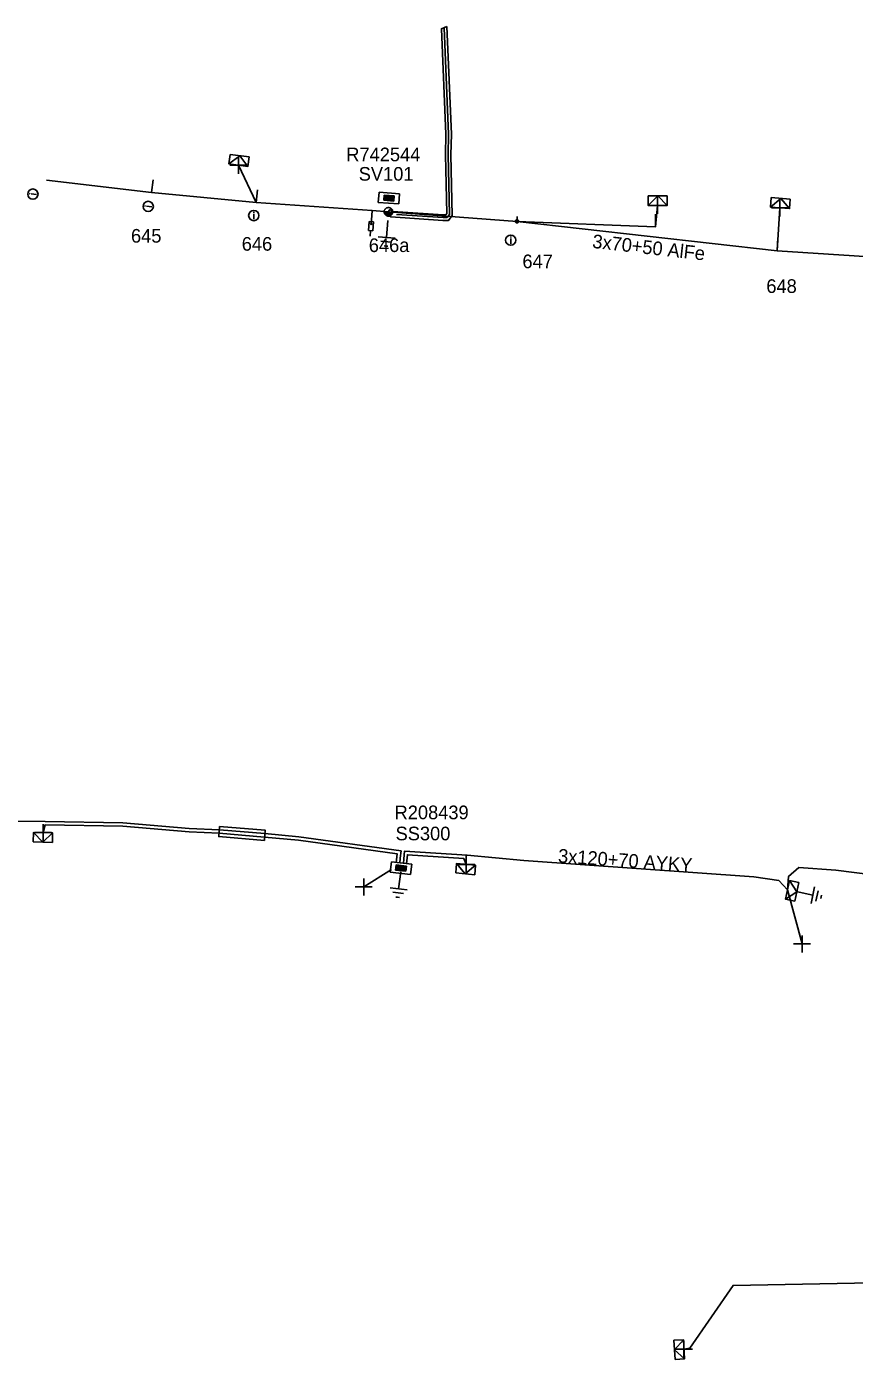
# Model space of a CAD drawing. Extents: x -540466 to -537383, y -1184038 to -1179972.
# Drawn here: x -538715.9 to -538655.3, y -1180219.4 to -1180121.7 of the extents above; entities that cross this region are included whole.
import ezdxf

# ---------------------------------------------------------------- set-up
doc = ezdxf.new("R2010")
doc.units = 0
for name, color, linetype in [('Vrstva 1', 7, 'Continuous'), ('Vrstva 10', 7, 'Continuous'), ('Vrstva 13', 7, 'Continuous'), ('Vrstva 14', 7, 'Continuous'), ('Vrstva 15', 7, 'Continuous'), ('Vrstva 16', 7, 'Continuous'), ('Vrstva 2', 7, 'Continuous'), ('Vrstva 20', 7, 'Continuous'), ('Vrstva 28', 7, 'Continuous'), ('Vrstva 29', 7, 'Continuous'), ('Vrstva 30', 7, 'Continuous'), ('Vrstva 31', 7, 'Continuous'), ('Vrstva 34', 7, 'Continuous'), ('Vrstva 36', 7, 'Continuous'), ('Vrstva 5', 7, 'Continuous'), ('Vrstva 52', 7, 'Continuous'), ('Vrstva 54', 7, 'Continuous'), ('Vrstva 59', 7, 'Continuous'), ('Vrstva 6', 7, 'Continuous'), ('Vrstva 8', 7, 'Continuous'), ('Vrstva 9', 7, 'Continuous')]:
    doc.layers.add(name, color=color, linetype=linetype)

# ---------------------------------------------------------------- blocks, each defined once
blk = doc.blocks.new('NN440')
at = {"layer": 'Vrstva 2'}
for points in [[(0.63, 0), (0.63, 0.06), (0.62, 0.13), (0.6, 0.19), (0.58, 0.25), (0.55, 0.31), (0.51, 0.37), (0.47, 0.42), (0.42, 0.46), (0.37, 0.51), (0.32, 0.54), (0.26, 0.57), (0.2, 0.59), (0.13, 0.61), (0.07, 0.62), (0, 0.63), (-0.06, 0.62), (-0.13, 0.61), (-0.19, 0.59), (-0.26, 0.57), (-0.31, 0.54), (-0.37, 0.51), (-0.42, 0.46), (-0.47, 0.42), (-0.51, 0.37), (-0.54, 0.31), (-0.57, 0.25), (-0.6, 0.19), (-0.62, 0.13), (-0.63, 0.06), (-0.63, 0), (-0.63, -0.07), (-0.62, -0.14), (-0.6, -0.2), (-0.57, -0.26), (-0.54, -0.32), (-0.51, -0.37), (-0.47, -0.43), (-0.42, -0.47), (-0.37, -0.51), (-0.31, -0.55), (-0.26, -0.58), (-0.19, -0.6), (-0.13, -0.62), (-0.06, -0.63), (0, -0.63), (0.07, -0.63), (0.13, -0.62), (0.2, -0.6), (0.26, -0.58), (0.32, -0.55), (0.37, -0.51), (0.42, -0.47), (0.47, -0.43), (0.51, -0.37), (0.55, -0.32), (0.58, -0.26), (0.6, -0.2), (0.62, -0.14), (0.63, -0.07), (0.63, 0)], [(-0.63, 0), (0.63, 0)], [(-0.6, -0.18), (0.57, -0.18)], [(-0.51, -0.32), (0.5, -0.32)], [(-0.37, -0.47), (0.35, -0.47)]]:
    blk.add_lwpolyline(points, dxfattribs=at)
blk = doc.blocks.new('NN770')
at = {"layer": 'Vrstva 10'}
for p, q in [((0.002, 0.187), (0.002, 0.263)), ((0.002, -0.276), (0.002, 0.111))]:
    blk.add_line(p, q, dxfattribs=at)
blk.add_circle((0, -0.008), 0.375, dxfattribs=at)
blk = doc.blocks.new('NN800')
at = {"layer": 'Vrstva 1'}
for points in [[(-0.442, 0.442), (0.442, -0.442)], [(-0.442, -0.442), (0.442, 0.442)]]:
    blk.add_lwpolyline(points, dxfattribs=at)
blk = doc.blocks.new('NN820')
at = {"layer": 'Vrstva 13'}
for points in [[(-0.003, 0.004), (-0.003, -1.049)], [(-0.165, -0.813), (0.165, -0.813)], [(-0.165, -1.473), (-0.165, -0.813)], [(-0.003, -1.049), (-0.062, -0.926)], [(-0.003, -1.049), (0.057, -0.926)], [(0.165, -0.813), (0.165, -1.473)], [(0.165, -1.473), (-0.165, -1.473)], [(-0.003, -1.473), (-0.003, -1.871)]]:
    blk.add_lwpolyline(points, dxfattribs=at)
blk = doc.blocks.new('NN620')
at = {"layer": 'Vrstva 8'}
for points in [[(0.752, 0.004), (-0.748, 0.004)], [(-0.748, 0.004), (-0.748, -0.746)], [(0.752, -0.746), (0.752, 0.004)], [(-0.748, -0.746), (0.752, -0.746)], [(0.368, -0.18), (-0.376, -0.18)], [(-0.376, -0.18), (-0.376, -0.558)], [(-0.376, -0.558), (0.368, -0.558)], [(0.321, -0.227), (-0.329, -0.227)], [(-0.329, -0.227), (-0.329, -0.51)], [(-0.329, -0.51), (0.321, -0.51)], [(0.274, -0.274), (-0.281, -0.274)], [(-0.281, -0.274), (-0.281, -0.463)], [(-0.281, -0.463), (0.274, -0.463)], [(0.227, -0.321), (-0.234, -0.321)], [(-0.234, -0.321), (-0.234, -0.416)], [(-0.234, -0.416), (0.227, -0.416)], [(-0.193, -0.369), (0.185, -0.369)], [(0.227, -0.416), (0.227, -0.321)], [(0.274, -0.463), (0.274, -0.274)], [(0.321, -0.51), (0.321, -0.227)], [(0.368, -0.558), (0.368, -0.18)]]:
    blk.add_lwpolyline(points, dxfattribs=at)
blk = doc.blocks.new('NN630')
at = {"layer": 'Vrstva 9'}
for points in [[(-0.003, -0.7), (-0.703, 0)], [(-0.703, -0.7), (-0.703, 0), (0.697, 0), (0.697, -0.7)], [(-0.703, -0.7), (0.697, -0.7)], [(-0.003, -0.7), (0.697, 0)]]:
    blk.add_lwpolyline(points, dxfattribs=at)
blk = doc.blocks.new('NN810')
at = {"layer": 'Vrstva 14'}
for points in [[(0.004, -0.64), (0.004, -1.89)], [(0.629, -1.89), (-0.621, -1.89)], [(0.388, -2.2), (-0.399, -2.2)], [(0.004, -2.515), (-0.124, -2.515)], [(0.137, -2.515), (0.004, -2.515)]]:
    blk.add_lwpolyline(points, dxfattribs=at)
blk = doc.blocks.new('NN500')
at = {"layer": 'Vrstva 2'}
for points in [[(0, -0.24), (0.02, -0.23), (0.05, -0.23), (0.07, -0.22), (0.09, -0.22), (0.12, -0.2), (0.14, -0.19), (0.16, -0.18), (0.17, -0.16), (0.19, -0.14), (0.2, -0.12), (0.21, -0.1), (0.22, -0.07), (0.23, -0.05), (0.23, -0.02), (0.23, 0), (0.23, 0.02), (0.23, 0.05), (0.22, 0.07), (0.21, 0.1), (0.2, 0.12), (0.19, 0.14), (0.17, 0.16), (0.16, 0.17), (0.14, 0.19), (0.12, 0.2), (0.09, 0.21), (0.07, 0.22), (0.05, 0.23), (0.02, 0.23), (0, 0.23), (-0.03, 0.23), (-0.05, 0.23), (-0.07, 0.22), (-0.1, 0.21), (-0.12, 0.2), (-0.14, 0.19), (-0.16, 0.17), (-0.18, 0.16), (-0.19, 0.14), (-0.2, 0.12), (-0.22, 0.1), (-0.22, 0.07), (-0.23, 0.05), (-0.23, 0.02), (-0.24, 0), (-0.23, -0.02), (-0.23, -0.05), (-0.22, -0.07), (-0.22, -0.1), (-0.2, -0.12), (-0.19, -0.14), (-0.18, -0.16), (-0.16, -0.18), (-0.14, -0.19), (-0.12, -0.2), (-0.1, -0.22), (-0.07, -0.22), (-0.05, -0.23), (-0.03, -0.23), (0, -0.24)], [(0, -0.24), (0.02, -0.23), (0.05, -0.23), (0.07, -0.22), (0.09, -0.22), (0.12, -0.2), (0.14, -0.19), (0.16, -0.18), (0.17, -0.16), (0.19, -0.14), (0.2, -0.12), (0.21, -0.1), (0.22, -0.07), (0.23, -0.05), (0.23, -0.02), (0.23, 0), (0.23, 0.02), (0.23, 0.05), (0.22, 0.07), (0.21, 0.1), (0.2, 0.12), (0.19, 0.14), (0.17, 0.16), (0.16, 0.17), (0.14, 0.19), (0.12, 0.2), (0.09, 0.21), (0.07, 0.22), (0.05, 0.23), (0.02, 0.23), (0, 0.23), (-0.03, 0.23), (-0.05, 0.23), (-0.07, 0.22), (-0.1, 0.21), (-0.12, 0.2), (-0.14, 0.19), (-0.16, 0.17), (-0.18, 0.16), (-0.19, 0.14), (-0.2, 0.12), (-0.22, 0.1), (-0.22, 0.07), (-0.23, 0.05), (-0.23, 0.02), (-0.24, 0), (-0.23, -0.02), (-0.23, -0.05), (-0.22, -0.07), (-0.22, -0.1), (-0.2, -0.12), (-0.19, -0.14), (-0.18, -0.16), (-0.16, -0.18), (-0.14, -0.19), (-0.12, -0.2), (-0.1, -0.22), (-0.07, -0.22), (-0.05, -0.23), (-0.03, -0.23), (0, -0.24)], [(0, -0.21), (0.02, -0.2), (0.04, -0.2), (0.06, -0.2), (0.08, -0.19), (0.1, -0.18), (0.12, -0.17), (0.14, -0.15), (0.15, -0.14), (0.16, -0.12), (0.18, -0.1), (0.19, -0.08), (0.19, -0.06), (0.2, -0.04), (0.2, -0.02), (0.2, 0), (0.2, 0.02), (0.2, 0.04), (0.19, 0.06), (0.19, 0.08), (0.18, 0.1), (0.16, 0.12), (0.15, 0.14), (0.14, 0.15), (0.12, 0.17), (0.1, 0.18), (0.08, 0.19), (0.06, 0.19), (0.04, 0.2), (0.02, 0.2), (0, 0.2), (-0.02, 0.2), (-0.04, 0.2), (-0.06, 0.19), (-0.08, 0.19), (-0.1, 0.18), (-0.12, 0.17), (-0.14, 0.15), (-0.15, 0.14), (-0.17, 0.12), (-0.18, 0.1), (-0.19, 0.08), (-0.2, 0.06), (-0.2, 0.04), (-0.21, 0.02), (-0.21, 0), (-0.21, -0.02), (-0.2, -0.04), (-0.2, -0.06), (-0.19, -0.08), (-0.18, -0.1), (-0.17, -0.12), (-0.15, -0.14), (-0.14, -0.15), (-0.12, -0.17), (-0.1, -0.18), (-0.08, -0.19), (-0.06, -0.2), (-0.04, -0.2), (-0.02, -0.2), (0, -0.21)], [(0, -0.18), (0.02, -0.18), (0.04, -0.17), (0.05, -0.17), (0.07, -0.16), (0.09, -0.15), (0.1, -0.14), (0.12, -0.13), (0.13, -0.12), (0.14, -0.1), (0.15, -0.09), (0.16, -0.07), (0.17, -0.05), (0.17, -0.04), (0.17, -0.02), (0.17, 0), (0.17, 0.02), (0.17, 0.04), (0.17, 0.05), (0.16, 0.07), (0.15, 0.09), (0.14, 0.1), (0.13, 0.12), (0.12, 0.13), (0.1, 0.14), (0.09, 0.15), (0.07, 0.16), (0.05, 0.17), (0.04, 0.17), (0.02, 0.17), (0, 0.18), (-0.02, 0.17), (-0.04, 0.17), (-0.06, 0.17), (-0.07, 0.16), (-0.09, 0.15), (-0.1, 0.14), (-0.12, 0.13), (-0.13, 0.12), (-0.14, 0.1), (-0.15, 0.09), (-0.16, 0.07), (-0.17, 0.05), (-0.17, 0.04), (-0.18, 0.02), (-0.18, 0), (-0.18, -0.02), (-0.17, -0.04), (-0.17, -0.05), (-0.16, -0.07), (-0.15, -0.09), (-0.14, -0.1), (-0.13, -0.12), (-0.12, -0.13), (-0.1, -0.14), (-0.09, -0.15), (-0.07, -0.16), (-0.06, -0.17), (-0.04, -0.17), (-0.02, -0.18), (0, -0.18)], [(0, -0.15), (0.01, -0.15), (0.03, -0.14), (0.04, -0.14), (0.06, -0.13), (0.07, -0.13), (0.08, -0.12), (0.1, -0.11), (0.11, -0.1), (0.12, -0.09), (0.13, -0.07), (0.13, -0.06), (0.14, -0.05), (0.14, -0.03), (0.14, -0.02), (0.14, 0), (0.14, 0.01), (0.14, 0.03), (0.14, 0.04), (0.13, 0.06), (0.13, 0.07), (0.12, 0.09), (0.11, 0.1), (0.1, 0.11), (0.08, 0.12), (0.07, 0.13), (0.06, 0.13), (0.04, 0.14), (0.03, 0.14), (0.01, 0.14), (0, 0.15), (-0.02, 0.14), (-0.03, 0.14), (-0.05, 0.14), (-0.06, 0.13), (-0.07, 0.13), (-0.09, 0.12), (-0.1, 0.11), (-0.11, 0.1), (-0.12, 0.09), (-0.13, 0.07), (-0.13, 0.06), (-0.14, 0.04), (-0.14, 0.03), (-0.15, 0.01), (-0.15, 0), (-0.15, -0.02), (-0.14, -0.03), (-0.14, -0.05), (-0.13, -0.06), (-0.13, -0.07), (-0.12, -0.09), (-0.11, -0.1), (-0.1, -0.11), (-0.09, -0.12), (-0.07, -0.13), (-0.06, -0.13), (-0.05, -0.14), (-0.03, -0.14), (-0.02, -0.15), (0, -0.15)], [(0, -0.12), (0.01, -0.12), (0.02, -0.11), (0.03, -0.11), (0.05, -0.11), (0.06, -0.1), (0.07, -0.09), (0.08, -0.09), (0.09, -0.08), (0.09, -0.07), (0.1, -0.06), (0.11, -0.05), (0.11, -0.04), (0.11, -0.02), (0.11, -0.01), (0.12, 0), (0.11, 0.01), (0.11, 0.02), (0.11, 0.04), (0.11, 0.05), (0.1, 0.06), (0.09, 0.07), (0.09, 0.08), (0.08, 0.09), (0.07, 0.09), (0.06, 0.1), (0.05, 0.11), (0.03, 0.11), (0.02, 0.11), (0.01, 0.12), (0, 0.12), (-0.01, 0.12), (-0.03, 0.11), (-0.04, 0.11), (-0.05, 0.11), (-0.06, 0.1), (-0.07, 0.09), (-0.08, 0.09), (-0.09, 0.08), (-0.1, 0.07), (-0.1, 0.06), (-0.11, 0.05), (-0.11, 0.04), (-0.12, 0.02), (-0.12, 0.01), (-0.12, 0), (-0.12, -0.01), (-0.12, -0.02), (-0.11, -0.04), (-0.11, -0.05), (-0.1, -0.06), (-0.1, -0.07), (-0.09, -0.08), (-0.08, -0.09), (-0.07, -0.09), (-0.06, -0.1), (-0.05, -0.11), (-0.04, -0.11), (-0.03, -0.11), (-0.01, -0.12), (0, -0.12)], [(0, -0.09), (0.01, -0.09), (0.02, -0.09), (0.03, -0.08), (0.03, -0.08), (0.04, -0.08), (0.05, -0.07), (0.06, -0.07), (0.06, -0.06), (0.07, -0.05), (0.07, -0.04), (0.08, -0.04), (0.08, -0.03), (0.08, -0.02), (0.09, -0.01), (0.09, 0), (0.09, 0.01), (0.08, 0.02), (0.08, 0.03), (0.08, 0.03), (0.07, 0.04), (0.07, 0.05), (0.06, 0.06), (0.06, 0.06), (0.05, 0.07), (0.04, 0.07), (0.03, 0.08), (0.03, 0.08), (0.02, 0.08), (0.01, 0.09), (0, 0.09), (-0.01, 0.09), (-0.02, 0.08), (-0.03, 0.08), (-0.04, 0.08), (-0.04, 0.07), (-0.05, 0.07), (-0.06, 0.06), (-0.07, 0.06), (-0.07, 0.05), (-0.08, 0.04), (-0.08, 0.03), (-0.08, 0.03), (-0.09, 0.02), (-0.09, 0.01), (-0.09, 0), (-0.09, -0.01), (-0.09, -0.02), (-0.08, -0.03), (-0.08, -0.04), (-0.08, -0.04), (-0.07, -0.05), (-0.07, -0.06), (-0.06, -0.07), (-0.05, -0.07), (-0.04, -0.08), (-0.04, -0.08), (-0.03, -0.08), (-0.02, -0.09), (-0.01, -0.09), (0, -0.09)], [(0, -0.06), (0, -0.06), (0.01, -0.06), (0.02, -0.05), (0.02, -0.05), (0.03, -0.05), (0.03, -0.05), (0.04, -0.04), (0.04, -0.04), (0.05, -0.03), (0.05, -0.03), (0.05, -0.02), (0.05, -0.02), (0.05, -0.01), (0.06, -0.01), (0.06, 0), (0.06, 0.01), (0.05, 0.01), (0.05, 0.02), (0.05, 0.02), (0.05, 0.03), (0.05, 0.03), (0.04, 0.04), (0.04, 0.04), (0.03, 0.05), (0.03, 0.05), (0.02, 0.05), (0.02, 0.05), (0.01, 0.06), (0, 0.06), (0, 0.06), (-0.01, 0.06), (-0.01, 0.06), (-0.02, 0.05), (-0.02, 0.05), (-0.03, 0.05), (-0.03, 0.05), (-0.04, 0.04), (-0.04, 0.04), (-0.05, 0.03), (-0.05, 0.03), (-0.05, 0.02), (-0.06, 0.02), (-0.06, 0.01), (-0.06, 0.01), (-0.06, 0), (-0.06, -0.01), (-0.06, -0.01), (-0.06, -0.02), (-0.05, -0.02), (-0.05, -0.03), (-0.05, -0.03), (-0.04, -0.04), (-0.04, -0.04), (-0.03, -0.05), (-0.03, -0.05), (-0.02, -0.05), (-0.02, -0.05), (-0.01, -0.06), (-0.01, -0.06), (0, -0.06)], [(0, -0.03), (0, -0.03), (0, -0.03), (0.01, -0.03), (0.01, -0.03), (0.01, -0.02), (0.02, -0.02), (0.02, -0.02), (0.02, -0.02), (0.02, -0.02), (0.02, -0.01), (0.02, -0.01), (0.03, -0.01), (0.03, -0.01), (0.03, 0), (0.03, 0), (0.03, 0), (0.03, 0.01), (0.03, 0.01), (0.02, 0.01), (0.02, 0.01), (0.02, 0.02), (0.02, 0.02), (0.02, 0.02), (0.02, 0.02), (0.01, 0.02), (0.01, 0.02), (0.01, 0.03), (0, 0.03), (0, 0.03), (0, 0.03), (0, 0.03), (-0.01, 0.03), (-0.01, 0.03), (-0.01, 0.02), (-0.02, 0.02), (-0.02, 0.02), (-0.02, 0.02), (-0.02, 0.02), (-0.02, 0.02), (-0.03, 0.01), (-0.03, 0.01), (-0.03, 0.01), (-0.03, 0.01), (-0.03, 0), (-0.03, 0), (-0.03, 0), (-0.03, -0.01), (-0.03, -0.01), (-0.03, -0.01), (-0.03, -0.01), (-0.02, -0.02), (-0.02, -0.02), (-0.02, -0.02), (-0.02, -0.02), (-0.02, -0.02), (-0.01, -0.03), (-0.01, -0.03), (-0.01, -0.03), (0, -0.03), (0, -0.03)], [(0.23, 0), (0.7, 0)]]:
    blk.add_lwpolyline(points, dxfattribs=at)
blk = doc.blocks.new('NN510')
at = {"layer": 'Vrstva 2'}
blk.add_lwpolyline([(0.001, 0.002), (0.001, 0.939)], dxfattribs=at)

msp = doc.modelspace()

# ---------------------------------------------------------------- linework, layer by layer
at = {"layer": 'Vrstva 1'}
for points in [[(-538689.39, -1180135.29), (-538690.588, -1180135.207), (-538699.09, -1180134.62), (-538706.745, -1180133.873), (-538714.434, -1180132.968)], [(-538592.137, -1180148.014), (-538615.217, -1180144.633), (-538626.671, -1180142.279), (-538638.304, -1180139.964), (-538653.378, -1180138.65), (-538660.91, -1180138.14), (-538679.97, -1180135.99), (-538689.39, -1180135.29)]]:
    msp.add_lwpolyline(points, dxfattribs=at)
at = {"layer": 'Vrstva 20'}
for points in [[(-538685.119, -1180121.723), (-538684.78, -1180129.598), (-538684.82, -1180131.12), (-538684.718, -1180135.554), (-538684.989, -1180135.92), (-538685.397, -1180135.92), (-538689.208, -1180135.656), (-538689.502, -1180135.455), (-538689.278, -1180135.125), (-538689.072, -1180135.264), (-538685.383, -1180135.52), (-538685.191, -1180135.52), (-538685.122, -1180135.426), (-538685.22, -1180131.12), (-538685.18, -1180129.602), (-538685.513, -1180121.874)], [(-538701.759, -1180180.331), (-538698.419, -1180180.611), (-538698.482, -1180181.358), (-538701.822, -1180181.078)]]:
    msp.add_lwpolyline(points, close=True, dxfattribs=at)
at = {"layer": 'Vrstva 5'}
for points in [[(-538688.799, -1180135.484), (-538685.39, -1180135.72), (-538685.09, -1180135.72), (-538684.92, -1180135.49), (-538685.02, -1180131.12), (-538684.98, -1180129.6), (-538685.316, -1180121.798)], [(-538688.555, -1180183.02), (-538688.519, -1180182.672), (-538688.463, -1180182.126), (-538695.95, -1180181.09), (-538698.44, -1180180.86), (-538701.78, -1180180.58), (-538703.98, -1180180.49), (-538708.85, -1180180.07), (-538714.54, -1180179.97), (-538721.22, -1180179.91), (-538723.94, -1180179.71), (-538725.01, -1180179.82), (-538731.54, -1180179.77), (-538732.42, -1180179.74), (-538732.76, -1180179.68), (-538736.482, -1180179.595), (-538736.485, -1180179.976), (-538736.493, -1180180.306)], [(-538660.145, -1180184.979), (-538660.79, -1180184.3), (-538662.62, -1180184.02), (-538679.48, -1180182.83), (-538683.61, -1180182.45), (-538688.215, -1180182.148), (-538688.266, -1180182.706), (-538688.298, -1180183.055)], [(-538660.145, -1180184.979), (-538660.07, -1180184), (-538659.32, -1180183.34), (-538656.61, -1180183.53), (-538650.09, -1180184.38), (-538644.38, -1180185.19), (-538643.11, -1180185.75), (-538641.01, -1180186.4), (-538637.53, -1180186.77), (-538632.17, -1180187.29), (-538630.37, -1180187.62), (-538628.03, -1180188.36), (-538627.45, -1180188.84), (-538627.42, -1180189.93), (-538627.84, -1180195.3), (-538628.14, -1180200.7), (-538628.49, -1180208.43), (-538629.329, -1180214.169), (-538634.793, -1180213.068), (-538635.003, -1180212.736), (-538635.006, -1180212.042), (-538635.007, -1180211.842)]]:
    msp.add_lwpolyline(points, dxfattribs=at)
at = {"layer": 'Vrstva 52'}
for points in [[(-538688.823, -1180183.006), (-538688.762, -1180182.336), (-538695.978, -1180181.339), (-538698.462, -1180181.109), (-538701.795, -1180180.829), (-538703.996, -1180180.739), (-538708.863, -1180180.32), (-538714.543, -1180180.22), (-538714.693, -1180180.79)], [(-538688.063, -1180183.078), (-538687.995, -1180182.412), (-538683.877, -1180182.682), (-538683.697, -1180183.112)], [(-538635.531, -1180211.829), (-538635.539, -1180212.328), (-538636.206, -1180213.432), (-538664.139, -1180213.965), (-538667.303, -1180218.579), (-538667.737, -1180218.65)]]:
    msp.add_lwpolyline(points, dxfattribs=at)
at = {"layer": 'Vrstva 54'}
for points in [[(-538699.09, -1180134.62), (-538700.385, -1180131.872)], [(-538679.97, -1180135.99), (-538669.834, -1180136.394), (-538669.666, -1180134.825)], [(-538660.91, -1180138.14), (-538660.701, -1180135.002)]]:
    msp.add_lwpolyline(points, dxfattribs=at)
at = {"layer": 'Vrstva 59'}
for points in [[(-538689.157, -1180183.488), (-538691.2, -1180184.772)], [(-538660.145, -1180184.979), (-538659.08, -1180188.946)]]:
    msp.add_lwpolyline(points, dxfattribs=at)

# ---------------------------------------------------------------- block references
at = {"layer": 'Vrstva 13'}
for p, rotation in [((-538706.746, -1180133.873), -7.308902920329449), ((-538699.09, -1180134.62), -7.134233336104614), ((-538669.834, -1180136.395), -0.2026443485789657), ((-538660.911, -1180138.14), -2.429741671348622)]:
    msp.add_blockref('NN510', p, dxfattribs=dict(at, rotation=rotation))
for name, p, xscale, yscale, rotation in [('NN440', (-538689.39, -1180135.29), 0.5, 0.5000000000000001, -4.249837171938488), ('NN500', (-538679.97, -1180135.99), 0.5000000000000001, 0.5, 88.29099999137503)]:
    msp.add_blockref(name, p, dxfattribs=dict(at, xscale=xscale, yscale=yscale, rotation=rotation))
at = {"layer": 'Vrstva 15'}
for p, rotation in [((-538689.39, -1180135.29), -4.249837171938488), ((-538688.421, -1180183.025), -6.830208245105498), ((-538660.145, -1180184.979), 78.16883331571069)]:
    msp.add_blockref('NN810', p, dxfattribs=dict(at, rotation=rotation))
at = {"layer": 'Vrstva 16', "rotation": -3.9510491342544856}
msp.add_blockref('NN820', (-538690.588, -1180135.207), dxfattribs=at)
at = {"layer": 'Vrstva 28'}
for p, rotation in [((-538689.381, -1180134.653), 175.75016282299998), ((-538688.421, -1180183.025), -6.830208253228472)]:
    msp.add_blockref('NN620', p, dxfattribs=dict(at, rotation=rotation))
at = {"layer": 'Vrstva 31'}
for p, rotation in [((-538700.385, -1180131.872), 172.52602221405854), ((-538669.666, -1180134.824), 179.7973556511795), ((-538660.701, -1180135.002), 175.32325831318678), ((-538714.693, -1180180.79), -1.4059638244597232), ((-538683.697, -1180183.112), -5.475172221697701), ((-538660.145, -1180184.979), 78.16883338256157), ((-538667.737, -1180218.65), -86.50426668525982)]:
    msp.add_blockref('NN630', p, dxfattribs=dict(at, rotation=rotation))
at = {"layer": 'Vrstva 34'}
for p, rotation in [((-538700.385, -1180131.872), 45), ((-538669.666, -1180134.825), 45), ((-538660.701, -1180135.002), 45), ((-538714.693, -1180180.789), 45), ((-538683.697, -1180183.112), 45), ((-538691.2, -1180184.772), 44.99999995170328), ((-538659.08, -1180188.945), 44.99999995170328), ((-538667.737, -1180218.65), 45)]:
    msp.add_blockref('NN800', p, dxfattribs=dict(at, rotation=rotation))
at = {"layer": 'Vrstva 36'}
for p, rotation in [((-538715.449, -1180133.991), 82.33669173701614), ((-538706.996, -1180134.893), 82.70046391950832), ((-538699.258, -1180135.562), -0.23592236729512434), ((-538680.431, -1180137.363), -0.5465190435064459)]:
    msp.add_blockref('NN770', p, dxfattribs=dict(at, rotation=rotation))

# ---------------------------------------------------------------- texts
at = {"layer": 'Vrstva 14'}
for s, p in [('645', (-538708.254, -1180137.552)), ('646', (-538700.139, -1180138.141)), ('646a', (-538690.83, -1180138.24)), ('647', (-538679.574, -1180139.424)), ('648', (-538661.702, -1180141.237))]:
    msp.add_text(s, height=1, dxfattribs=at).set_placement(p)
at = {"layer": 'Vrstva 2'}
msp.add_text('3x70+50 AlFe', height=1, rotation=353.564, dxfattribs=at).set_placement((-538674.488, -1180137.931))
at = {"layer": 'Vrstva 29'}
for s, p in [('R742544', (-538692.479, -1180131.589)), ('R208439', (-538688.94, -1180179.805))]:
    msp.add_text(s, height=1, dxfattribs=at).set_placement(p)
at = {"layer": 'Vrstva 30'}
for s, p in [('SV101', (-538691.569, -1180133.01)), ('SS300', (-538688.868, -1180181.352))]:
    msp.add_text(s, height=1, dxfattribs=at).set_placement(p)
at = {"layer": 'Vrstva 6'}
msp.add_text('3x120+70 AYKY', height=1, rotation=355.963, dxfattribs=at).set_placement((-538676.988, -1180182.972))

doc.saveas('drawing.dxf')
